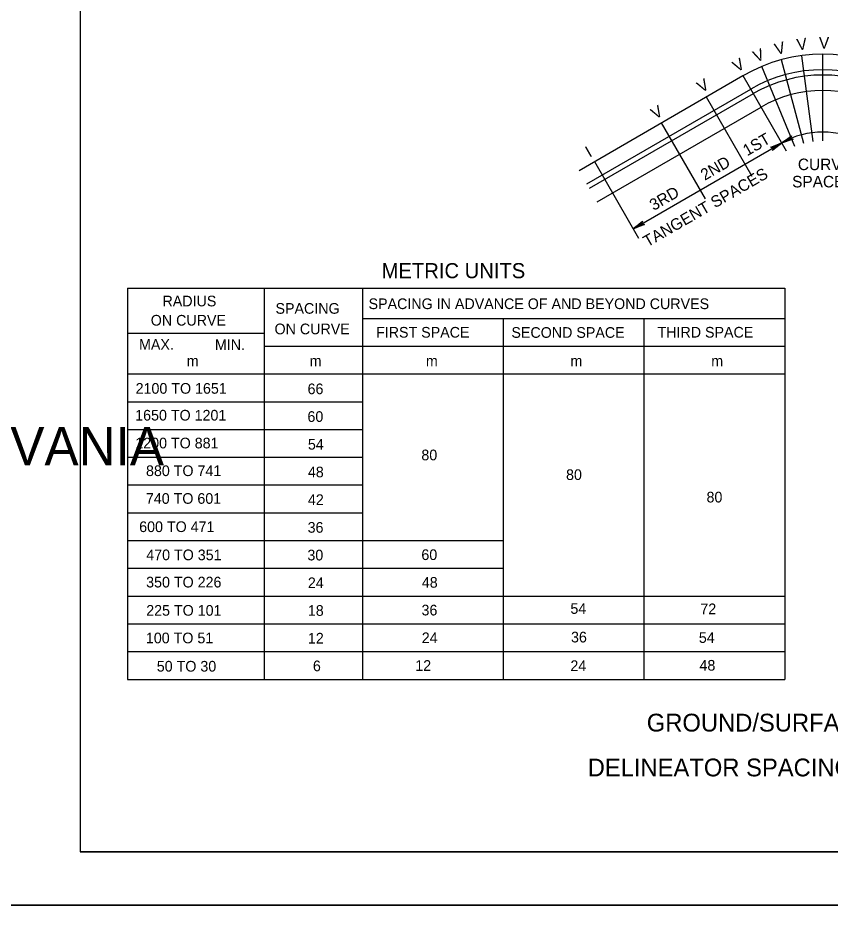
# Model space of a CAD drawing. Extents: x 640253 to 641999, y 298458 to 299646.
# Drawn here: x 641116.9 to 641345.5, y 299044.1 to 299301.1 of the extents above; entities that cross this region are included whole.
import ezdxf

# ---------------------------------------------------------------- set-up
doc = ezdxf.new("R2010")
doc.units = 0
for name, color, linetype in [('1', 7, 'Continuous'), ('2', 7, 'Continuous'), ('PLT-BNDY', 7, 'Continuous')]:
    doc.layers.add(name, color=color, linetype=linetype)

msp = doc.modelspace()

# ---------------------------------------------------------------- linework, layer by layer
at = {"layer": '1'}
for p, q in [((641134.31, 299630.63), (641134.31, 299066.63)), ((641920.31, 299066.63), (641134.31, 299066.63)), ((641134.31, 299066.63), (641720.31, 299066.63))]:
    msp.add_line(p, q, dxfattribs=at)
at = {"layer": '2'}
for p, q in [((641340.6, 299266.44), (641337.42, 299290.61)), ((641343.28, 299266.62), (641343.28, 299291.01)), ((641337.97, 299265.93), (641331.67, 299289.46)), ((641335.42, 299265.08), (641326.1, 299287.59)), ((641274.69, 299258.34), (641320.84, 299284.99)), ((641320.84, 299284.99), (641333.02, 299263.86)), ((641276.86, 299254.58), (641323.01, 299281.22)), ((641277.6, 299253.29), (641323.76, 299279.93)), ((641310.5, 299279.03), (641323.36, 299256.71)), ((641279.78, 299249.53), (641325.93, 299276.17)), ((641297.81, 299271.71), (641310.15, 299250.32)), ((641289.95, 299241.9), (641331.78, 299266.05)), ((641279.01, 299260.88), (641291.46, 299239.28)), ((641147.6, 299225.24), (641147.6, 299115.14)), ((641147.6, 299225.24), (641332.61, 299225.24)), ((641186.09, 299225.24), (641186.09, 299115.14)), ((641213.74, 299225.24), (641213.74, 299115.14)), ((641332.61, 299225.24), (641332.61, 299115.14)), ((641213.74, 299216.68), (641332.61, 299216.68)), ((641218.56, 299216.68), (641218.56, 299216.68)), ((641253.34, 299216.68), (641253.34, 299115.14)), ((641253.9, 299216.68), (641253.9, 299216.68)), ((641289.23, 299216.68), (641289.23, 299216.68)), ((641292.94, 299216.68), (641292.94, 299115.14)), ((641324.57, 299216.68), (641324.57, 299216.68)), ((641147.61, 299212.58), (641186.16, 299212.58)), ((641186.09, 299208.87), (641332.61, 299208.87)), ((641147.6, 299201.06), (641332.61, 299201.06)), ((641147.6, 299193.25), (641213.74, 299193.25)), ((641147.6, 299185.44), (641213.74, 299185.44)), ((641147.6, 299177.63), (641213.74, 299177.63)), ((641147.6, 299169.82), (641213.74, 299169.82)), ((641147.6, 299162.01), (641213.74, 299162.01)), ((641147.6, 299154.2), (641253.34, 299154.2)), ((641147.6, 299146.38), (641253.34, 299146.38)), ((641147.6, 299138.57), (641332.61, 299138.57)), ((641147.6, 299130.76), (641332.61, 299130.76)), ((641147.6, 299122.95), (641332.61, 299122.95)), ((641147.6, 299115.14), (641332.61, 299115.14))]:
    msp.add_line(p, q, dxfattribs=at)
for points in [[(641334.76, 299267.14), (641334.55, 299267.28), (641331.78, 299266.05), (641334.76, 299267.14), (641334.97, 299267.09), (641331.78, 299266.05), (641334.42, 299267.56), (641334.4, 299267.82), (641331.78, 299266.05), (641334.48, 299268.03), (641334.4, 299267.82)], [(641328.84, 299264.82), (641329.07, 299264.68), (641331.78, 299266.05), (641328.84, 299264.82), (641328.64, 299264.85), (641331.78, 299266.05), (641329.23, 299264.4), (641329.24, 299264.16), (641331.78, 299266.05), (641329.17, 299263.93), (641329.24, 299264.16)], [(641292.88, 299243.14), (641292.65, 299243.28), (641289.95, 299241.9), (641292.88, 299243.14), (641293.09, 299243.1), (641289.95, 299241.9), (641292.5, 299243.55), (641292.48, 299243.8), (641289.95, 299241.9), (641292.55, 299244.02), (641292.48, 299243.8)]]:
    msp.add_lwpolyline(points, dxfattribs=at)
for radius in [44.9, 40.55, 39.07, 34.71, 23.03]:
    msp.add_arc((641343.29, 299246.1), radius, 60.0122, 120.0089, dxfattribs=at)
at = {"layer": 'PLT-BNDY'}
for points in [[(641094.31, 299645.63), (641935.31, 299645.63), (641935.31, 299051.63), (641094.31, 299051.63)], [(641094.31, 299051.63), (641935.31, 299051.63), (641935.31, 298457.63), (641094.31, 298457.63)]]:
    msp.add_lwpolyline(points, close=True, dxfattribs=at)

# ---------------------------------------------------------------- texts
at = {"layer": '1'}
msp.add_text('COMMONWEALTH OF PENNSYLVANIA', height=10.7828, dxfattribs=at).set_placement((640891.9, 299175.36))
at = {"layer": '2'}
for s, height, rotation, p in [('V', 3.25, 7.491, (641336.17, 299292.07)), ('V', 3.25, 359.9889, (641342.22, 299292.61)), ('V', 3.25, 14.993, (641330.23, 299290.75)), ('V', 3.25, 22.4951, (641324.52, 299288.67)), ('V', 3.25, 29.9972, (641319.12, 299285.85)), ('V', 3.25, 29.9972, (641309.11, 299280.07)), ('V', 3.25, 29.9972, (641296.12, 299272.58)), ('1ST', 3.246, 29.9926, (641321.99, 299262.27)), ('I', 3.25, 29.9972, (641277.62, 299261.9)), ('2ND', 3.246, 29.9926, (641310.08, 299255.39)), ('TANGENT SPACES', 3.2458, 30, (641293.95, 299236.66)), ('3RD', 3.246, 29.9926, (641295.72, 299246.9))]:
    msp.add_text(s, height=height, rotation=rotation, dxfattribs=at).set_placement(p)
for s, height, p in [('CURVE', 3.246, (641336.29, 299258.41)), ('SPACES', 3.246, (641334.67, 299253.55)), ('METRIC UNITS', 4.25, (641219.14, 299228)), ('RADIUS', 3, (641157.45, 299220.08)), ('SPACING', 3, (641189.26, 299218)), ('SPACING IN ADVANCE OF AND BEYOND CURVES', 3, (641215.46, 299219.31)), ('ON CURVE', 3, (641154.15, 299214.67)), ('ON CURVE', 3, (641188.99, 299212.23)), ('FIRST SPACE', 3, (641217.56, 299211.29)), ('SECOND SPACE', 3, (641255.66, 299211.23)), ('THIRD SPACE', 3, (641296.78, 299211.3)), ('MAX.', 3, (641150.85, 299207.86)), ('MIN.', 3, (641172.22, 299207.79)), ('m', 3, (641164.27, 299203.24)), ('m', 3, (641198.87, 299203.24)), ('m', 3, (641231.59, 299203.24)), ('m', 3, (641272.27, 299203.24)), ('m', 3, (641311.91, 299203.24)), ('2100 TO 1651', 3, (641149.89, 299195.5)), ('66', 3, (641198.29, 299195.37)), ('1650 TO 1201', 3, (641149.77, 299187.95)), ('60', 3, (641198.25, 299187.57)), ('1200 TO 881', 3, (641149.8, 299180.12)), ('54', 3, (641198.38, 299179.78)), ('80', 3, (641230.32, 299176.77)), ('880 TO 741', 3, (641152.81, 299172.33)), ('48', 3, (641198.38, 299171.98)), ('80', 3, (641271.04, 299171.23)), ('740 TO 601', 3, (641152.78, 299164.53)), ('42', 3, (641198.38, 299164.19)), ('80', 3, (641310.58, 299164.91)), (' 600 TO 471', 3, (641149.78, 299156.58)), ('36', 3, (641198.3, 299156.39)), ('470 TO 351', 3, (641152.89, 299148.66)), ('30', 3, (641198.24, 299148.6)), ('60', 3, (641230.32, 299148.71)), ('350 TO 226', 3, (641152.85, 299140.99)), ('24', 3, (641198.37, 299140.8)), ('48', 3, (641230.45, 299140.92)), ('225 TO 101', 3, (641152.87, 299133.04)), ('18', 3, (641198.37, 299133.01)), ('36', 3, (641230.36, 299133.12)), ('54', 3, (641272.27, 299133.57)), ('72', 3, (641308.84, 299133.47)), ('100 TO 51', 3, (641152.78, 299125.28)), ('24', 3, (641230.43, 299125.33)), ('36', 3, (641272.44, 299125.52)), ('54', 3, (641308.42, 299125.39)), ('12', 3, (641198.38, 299125.21)), ('48', 3, (641308.6, 299117.59)), ('50 TO 30', 3, (641155.85, 299117.32)), ('6', 3, (641199.79, 299117.42)), (' 12', 3, (641227.49, 299117.53)), ('24', 3, (641272.27, 299117.47)), ('GROUND/SURFACE-MOUNTED', 5, (641293.76, 299100.46)), ('DELINEATOR SPACING ON CURVES', 5, (641277.13, 299087.84))]:
    msp.add_text(s, height=height, dxfattribs=at).set_placement(p)

doc.saveas('drawing.dxf')
